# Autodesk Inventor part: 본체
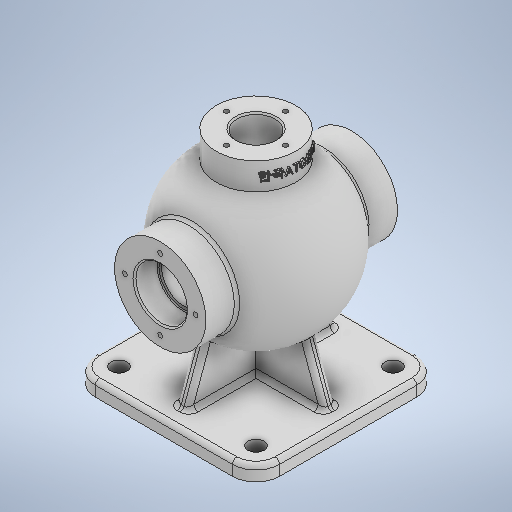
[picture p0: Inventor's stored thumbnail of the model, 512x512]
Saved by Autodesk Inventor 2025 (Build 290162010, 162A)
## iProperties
Created: 2024-07
Part Number: 본체
Material: 일반
Document SubType Name: Modeling
Designer: 학생
Density: 1 g/cm^3
Appearance: 기본값
Author: 학생
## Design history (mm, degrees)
sketch "스케치1"
  geometry: L1 (31, 0)-(34.965, 0); L2 (0, 65)-(0, 0); L3 (0, 44.838)-(0, -58.013); L4 (45.533, 0)-(-26.29, 0); L5 (0, 65)-(0, -65); L6 (0, 65)-(31, 65); L7 (31, -65)-(0, -65); L8 (0, -65)-(0, 65); L9 (31, 65)-(31, 44.215); L10 (31, -44.215)-(31, -65); A1 r 54 centre (0, 0) between (31, -44.215) and (31, 44.215); 4 further points
  constraints: 20 end point, 3 horizontal, 3 parallel, 3 point on line, 2 perpendicular, 2 point on circle, 1 centre point, 1 coincident, 1 midpoint, 1 symmetric about line
  dimensions: "d0" = 130 distance of L5.start L5.end; "d1" = 108 diameter of A1; "d2" = 31 distance of L7.start L7.end; "d3" = 130 distance of L6.end L7.start
revolve "회전1" sketch "스케치1" stored, may be unused: angle "d4" = 90 deg
fillet "모깎기1" dims "d5" = 3
node "작업 평면1"
sketch "스케치2"
  geometry: C1 r 27 at (0, 0); 1 further point
  constraints: 1 centre point, 1 coincident
  dimensions: "d7" = 54 diameter of C1
extrude "돌출1" join sketch "스케치2" stored distance "d8" = 10; taper "d9" = 0 deg
node "작업 평면2"
sketch "스케치3"
  geometry: L1 (-62.5, 62.5)-(62.5, 62.5); L2 (62.5, 62.5)-(62.5, -62.5); L3 (62.5, -62.5)-(-62.5, -62.5); L4 (-62.5, -62.5)-(-62.5, 62.5); L5 (-62.5, 62.5)-(62.5, -62.5); L6 (62.5, 62.5)-(-62.5, -62.5); C1 r 27 at (0, 0) reference; 1 further point
  constraints: 12 end point, 2 midpoint, 2 parallel, 1 horizontal, 1 perpendicular
  dimensions: "d11" = 125 distance of L2.end L3.end; "d12" = 125 distance of L1.end L2.end
extrude "돌출3" join sketch "스케치3" distance "d15" = 10; taper "d16" = 0 deg
fillet "모깎기2" dims "d17" = 16
sketch "스케치4"
  geometry: L1 (50.5, -4)-(-50.5, -4); L2 (-50.5, -4)-(-50.5, 4); L3 (-50.5, 4)-(50.5, 4); L4 (50.5, 4)-(50.5, -4); L5 (50.5, -4)-(-50.5, 4); L6 (-50.5, -4)-(50.5, 4); L7 (4, -50.5)-(-4, -50.5); L8 (-4, -50.5)-(-4, 50.5); L9 (-4, 50.5)-(4, 50.5); L10 (4, 50.5)-(4, -50.5); L11 (4, -50.5)-(-4, 50.5); L12 (-4, -50.5)-(4, 50.5); 1 further point
  constraints: 24 end point, 4 midpoint, 4 parallel, 2 horizontal, 2 perpendicular
  dimensions: "d18" = 101 distance of L2.end L3.end; "d19" = 8 distance of L1.end L2.end; "d20" = 8 distance of L8.end L9.end; "d21" = 101 distance of L7.end L8.end
extrude "돌출4" join sketch "스케치4" distance "d22" = 80; taper "d23" = 0 deg
feature "면 기울기1" dims angle "d24" = 20 deg
feature "면 기울기2" dims angle "d25" = 20 deg
extrude "돌출5" join sketch "스케치4" distance "d26" = 80; taper "d27" = 0 deg
feature "면 기울기3" dims angle "d28" = 20 deg
feature "면 기울기4" dims angle "d29" = 20 deg
sketch "스케치5"
  geometry: L1 (0, 65)-(0, -65); L2 (-31, -65)-(31, -65) reference; L3 (0, 65)-(17.5, 65); L4 (17.5, 65)-(17.5, 49); L5 (17.5, 49)-(0, 49); L6 (0, 49)-(0, 65); L7 (0, 49)-(15, 49); L8 (15, 49)-(15, 41.364); L9 (15, 41.364)-(0, 41.364); L10 (0, 41.364)-(0, 49); L11 (0, 0)-(21.875, 0); L12 (0, -65)-(17.5, -65); L13 (17.5, -65)-(17.5, -49); L14 (17.5, -49)-(0, -49); L15 (0, -49)-(0, -65); L16 (0, -49)-(15, -49); L17 (15, -49)-(15, -41.364); L18 (15, -41.364)-(0, -41.364); L19 (0, -41.364)-(0, -49); A1 r 44 centre (0, 0) between (15, -41.364) and (15, 41.364); 4 further points
  constraints: 36 end point, 6 symmetric about line, 4 parallel, 3 horizontal, 3 perpendicular, 2 midpoint, 2 point on circle, 1 centre point, 1 coincident
  dimensions: "d30" = 130 distance of L1.start L1.end; "d31" = 88 diameter of A1; "d32" = 16 distance between parallel lines of L3 L5; "d33" = 17.5 distance between parallel lines of L1 L4; "d34" = 15 distance between parallel lines of L1 L8
revolve "회전2" sketch "스케치5" stored, may be unused: angle "d35" = 90 deg
fillet "모깎기3" dims "d36" = 0.6
chamfer "모따기1" distance "d37" = 1; stored, may be unused: second distance "d38" = 2, angle "d39" = 45 deg
sketch "스케치6"
  geometry: L1 (0, 0)-(0, 24)
  constraints: 2 end point, 1 vertical
  dimensions: "d40" = 24 distance of L1.start L1.end
hole "구멍1" sketch "스케치6" at (0, 24) diameter "d41" = 3.242; stored, may be unused: countersink angle "d45" = 90 deg, drill point angle "d47" = 118 deg; dims "d42" = 12, "d43" = 4, "d44" = 2, "d46" = 15
sketch "스케치7"
  geometry: C1 r 13 at (0, 0); 1 further point
  constraints: 1 centre point, 1 coincident
  dimensions: "d51" = 26 diameter of C1
extrude "돌출6" cut sketch "스케치7" stored distance "d52" = 80; taper "d53" = 0 deg
sketch "스케치8"
  geometry: L1 (0, 0)-(-20, 0)
  constraints: 2 end point, 1 horizontal
  dimensions: "d54" = 20 distance of L1.start L1.end
hole "구멍2" sketch "스케치8" at (-20, 0) diameter "d55" = 3.242; stored, may be unused: countersink angle "d59" = 90 deg, drill point angle "d61" = 118 deg; dims "d56" = 9, "d57" = 4, "d58" = 2, "d60" = 11
fillet "모깎기4" dims "d65" = 3
fillet "모깎기5" dims "d66" = 3
node "작업 평면3"
sketch "스케치9"
  geometry: L1 (65, -27)-(65, 27) reference; L2 (65, -27)-(46.765, -27) reference; 2 further points
  constraints: 1 other
  dimensions: "d68" = 9 distance from line of L1 point (56, 0); "d69" = 27 distance from line of L2 point (56, 0)
feature "엠보싱1" sketch "스케치9" dims "d70" = 1, "d71" = 0
chamfer "모따기2" distance "d72" = 1; stored, may be unused: second distance "d73" = 2, angle "d74" = 45 deg
sketch "스케치10"
  geometry: L1 (-46.5, -62.5)-(46.5, -62.5) reference; L2 (62.5, -46.5)-(62.5, 46.5) reference; L3 (0, 0)-(0, -5.815); L4 (0, 0)-(-4.58, 0); L5 (0, 0)-(4.58, 0); C1 r 5.5 at (46.5, -46.5); C2 r 13 at (0, 0) reference; C3 r 5.5 at (-46.5, -46.5); C4 r 5.5 at (-46.5, 46.5); C5 r 5.5 at (46.5, 46.5); 1 further point
  constraints: 6 end point, 4 centre point, 4 symmetric about line, 1 horizontal, 1 vertical, 3 other
  dimensions: "d77" = 11 diameter of C1; "d78" = 16 distance from line of C1.centre L1; "d79" = 16 distance from line of L2 C1.centre
extrude "돌출8" cut sketch "스케치10" distance "d82" = 10; taper "d83" = 0 deg
node "솔리드1"
pattern_circular "원형 패턴1" dims angle "d49" = 360 deg
mirror "미러1"
pattern_circular "원형 패턴2" dims angle "d63" = 360 deg
feature "A9D066F2-1C7D-4E18-AEED-F7BC21143FA4" dims "d41" = 3.242, "d42" = 12, "d43" = 4, "d44" = 2, "d45" = 90 deg, "d46" = 15, "d47" = 118 deg
other parameters: "d6" = 65, "d10" = -85, "d67" = 93
